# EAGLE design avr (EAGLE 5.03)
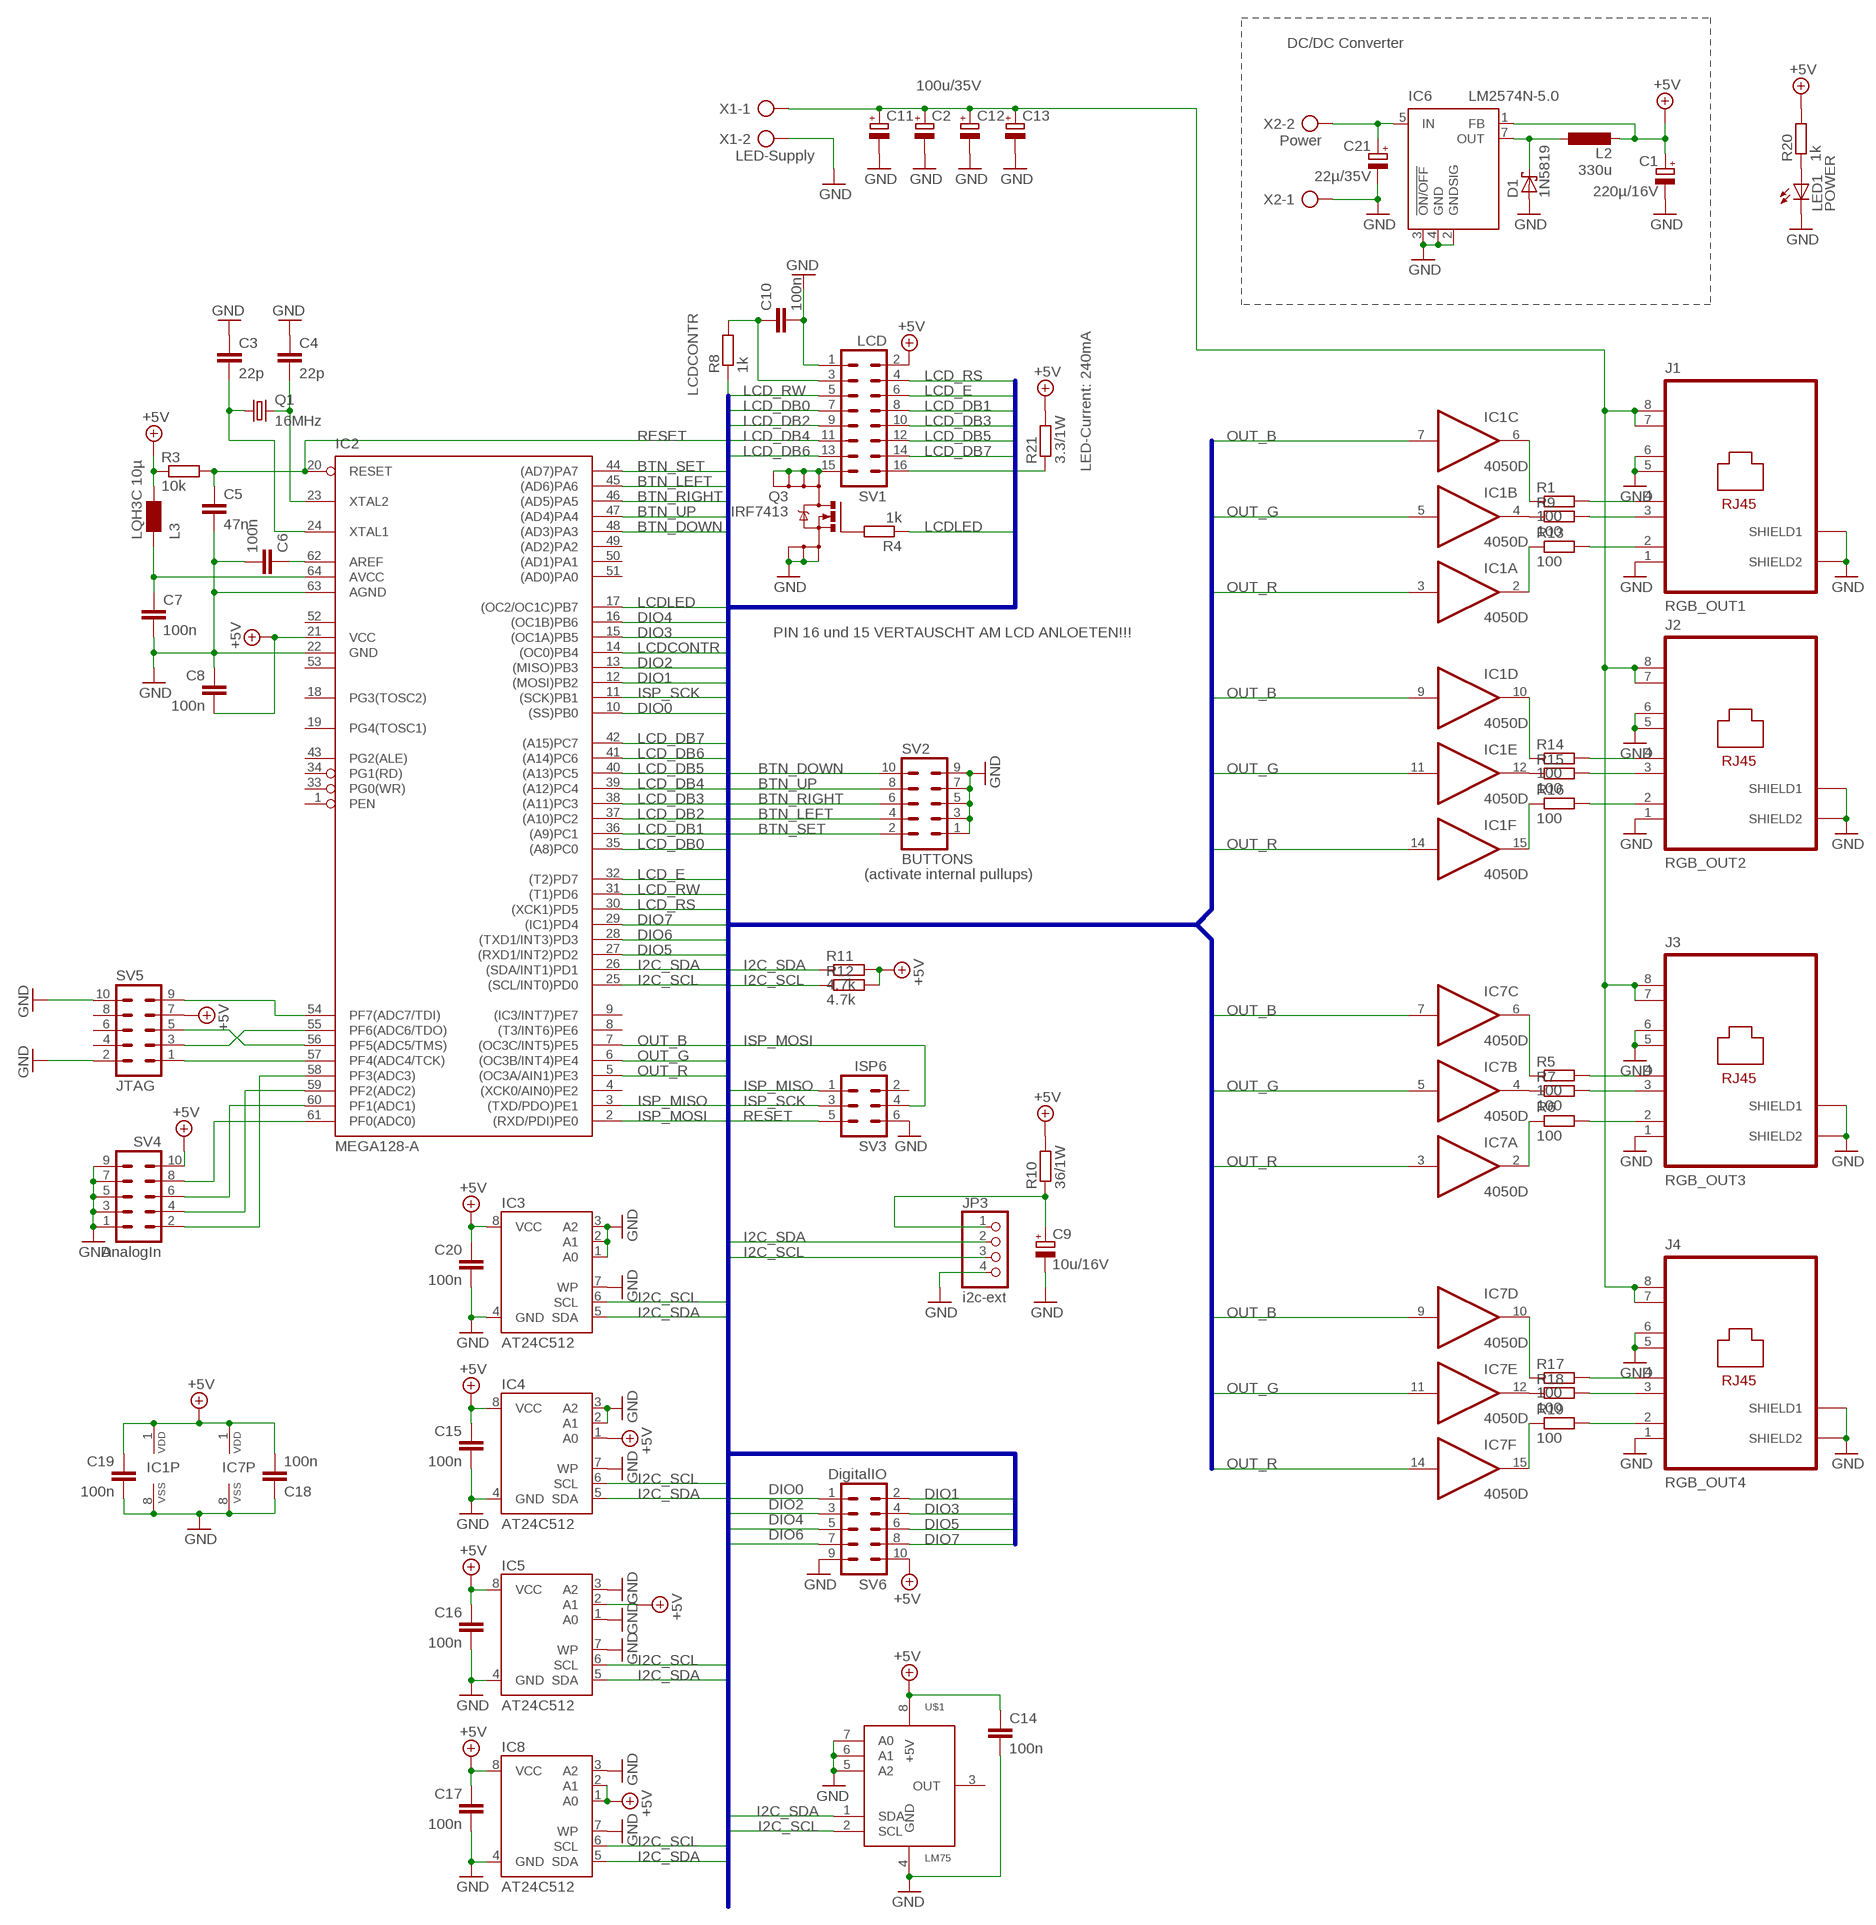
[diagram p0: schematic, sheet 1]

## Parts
C1  220µ/16V  CPOL-EUE2.5-7  [E2,5-7]
C2  100u/35V  CPOL-EUE2.5-7  [E2,5-7]
C3  22p  C-EUC1206  [C1206]
C4  22p  C-EUC1206  [C1206]
C5  47n  C-EUC1206  [C1206]
C6  100n  C-EUC1206  [C1206]
C7  100n  C-EUC1206  [C1206]
C8  100n  C-EUC1206  [C1206]
C9  10u/16V  CPOL-EUE2.5-5  [E2,5-5]
C10  100n  C-EUC1206  [C1206]
C11  100u/35V  CPOL-EUE2.5-7  [E2,5-7]
C12  100u/35V  CPOL-EUE2.5-7  [E2,5-7]
C13  100u/35V  CPOL-EUE2.5-7  [E2,5-7]
C14  100n  C-EUC1206  [C1206]
C15  100n  C-EUC1206  [C1206]
C16  100n  C-EUC1206  [C1206]
C17  100n  C-EUC1206  [C1206]
C18  100n  C-EUC1206  [C1206]
C19  100n  C-EUC1206  [C1206]
C20  100n  C-EUC1206  [C1206]
C21  22µ/35V  CPOL-EUE2.5-5  [E2,5-5]
D1  1N5819  SCHOTTKY-DIODEF126Z12  [F126Z12]
IC1  4050D  [SO16]
IC2  MEGA128-A  [TQFP64]
IC3  AT24C512  AT24CP  [DIL08]
IC4  AT24C512  AT24CP  [DIL08]
IC5  AT24C512  AT24CP  [DIL08]
IC6  LM2574N-5.0  [DIL08]
IC7  4050D  [SO16]
IC8  AT24C512  AT24CP  [DIL08]
J1  RGB_OUT1  MBEP8-8G  [MBEP8-8G]
J2  RGB_OUT2  MBEP8-8G  [MBEP8-8G]
J3  RGB_OUT3  MBEP8-8G  [MBEP8-8G]
J4  RGB_OUT4  MBEP8-8G  [MBEP8-8G]
JP3  i2c-ext  PINHD-1X4  [1X04]
L2  330u  L-EUPIS2816  [PIS2816]
L3  LQH3C 10µ  WE-CBF_1210  [1210]
LED1  POWER  LEDCHIPLED_1206  [CHIPLED_1206]
Q1  16MHz  CRYSTALHC49UP  [HC49UP]
Q3  IRF7413  [SO08]
R1  100  R-EU_R1206  [R1206]
R3  10k  R-EU_R1206  [R1206]
R4  1k  R-EU_R1206  [R1206]
R5  100  R-EU_R1206  [R1206]
R6  100  R-EU_R1206  [R1206]
R7  100  R-EU_R1206  [R1206]
R8  1k  R-EU_R1206  [R1206]
R9  100  R-EU_R1206  [R1206]
R10  36/1W  R-EU_0309/12  [0309/12]
R11  4.7k  R-EU_R1206  [R1206]
R12  4.7k  R-EU_R1206  [R1206]
R13  100  R-EU_R1206  [R1206]
R14  100  R-EU_R1206  [R1206]
R15  100  R-EU_R1206  [R1206]
R16  100  R-EU_R1206  [R1206]
R17  100  R-EU_R1206  [R1206]
R18  100  R-EU_R1206  [R1206]
R19  100  R-EU_R1206  [R1206]
R20  1k  R-EU_R1206  [R1206]
R21  3.3/1W  R-EU_0309/12  [0309/12]
SV1  LCD  ML16  [ML16]
SV2  BUTTONS  ML10  [ML10]
SV3  ISP6  ML6  [ML6]
SV4  AnalogIn  ML10  [ML10]
SV5  JTAG  ML10  [ML10]
SV6  DigitalIO  ML10  [ML10]
U$1  LM75  [SO8]
X1  LED-Supply  AK500/2  [AK500/2]
X2  Power  AK500/2  [AK500/2]

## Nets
+5V: C1.+ C8.2 C14.1 C15.1 C16.1 C17.1 C18.2 C19.1 C20.1 IC1.1(P:VDD) IC2.21(VCC) IC3.8(VCC) IC4.1(A0) IC4.8(VCC) IC5.2(A1) IC5.8(VCC) IC6.1(FB) IC7.1(P:VDD) IC8.1(A0) IC8.2(A1) IC8.8(VCC) L2.2 L3.2 R3.1 R10.2 R11.2 R12.2 R20.2 R21.2 SV1.2 SV4.10 SV5.7 SV6.10 U$1.8(+5V)
BTN_DOWN: IC2.48((AD3)PA3) SV2.10
BTN_LEFT: IC2.45((AD6)PA6) SV2.4
BTN_RIGHT: IC2.46((AD5)PA5) SV2.6
BTN_SET: IC2.44((AD7)PA7) SV2.2
BTN_UP: IC2.47((AD4)PA4) SV2.8
DIO0: IC2.10((SS)PB0) SV6.1
DIO1: IC2.12((MOSI)PB2) SV6.2
DIO2: IC2.13((MISO)PB3) SV6.3
DIO3: IC2.15((OC1A)PB5) SV6.4
DIO4: IC2.16((OC1B)PB6) SV6.5
DIO5: IC2.27((RXD1/INT2)PD2) SV6.6
DIO6: IC2.28((TXD1/INT3)PD3) SV6.7
DIO7: IC2.29((IC1)PD4) SV6.8
GND: C1.- C2.- C3.1 C4.1 C5.2 C6.2 C7.2 C8.1 C9.- C10.2 C11.- C12.- C13.- C14.2 C15.2 C16.2 C17.2 C18.1 C19.2 C20.2 C21.- D1.A IC1.8(P:VSS) IC2.22(GND) IC2.63(AGND) IC3.1(A0) IC3.2(A1) IC3.3(A2) IC3.4(GND) IC3.7(WP) IC4.2(A1) IC4.3(A2) IC4.4(GND) IC4.7(WP) IC5.1(A0) IC5.3(A2) IC5.4(GND) IC5.7(WP) IC6.2(GNDSIG) IC6.3(!ON/OFF) IC6.4(GND) IC7.8(P:VSS) IC8.3(A2) IC8.4(GND) IC8.7(WP) J1.1 J1.5 J1.6 J1.S1(SHIELD1) J1.S2(SHIELD2) J2.1 J2.5 J2.6 J2.S1(SHIELD1) J2.S2(SHIELD2) J3.1 J3.5 J3.6 J3.S1(SHIELD1) J3.S2(SHIELD2) J4.1 J4.5 J4.6 J4.S1(SHIELD1) J4.S2(SHIELD2) JP3.4 LED1.C Q3.1(S) Q3.2(S) Q3.3(S) SV1.1 SV2.1 SV2.3 SV2.5 SV2.7 SV2.9 SV3.6 SV4.1 SV4.3 SV4.5 SV4.7 SV4.9 SV5.2 SV5.10 SV6.9 U$1.4(GND) U$1.5(A2) U$1.6(A1) U$1.7(A0) X1.2 X2.1
I2C_SCL: IC2.25((SCL/INT0)PD0) IC3.6(SCL) IC4.6(SCL) IC5.6(SCL) IC8.6(SCL) JP3.3 R12.1 U$1.2(SCL)
I2C_SDA: IC2.26((SDA/INT1)PD1) IC3.5(SDA) IC4.5(SDA) IC5.5(SDA) IC8.5(SDA) JP3.2 R11.1 U$1.1(SDA)
ISP_MISO: IC2.3((TXD/PDO)PE1) SV3.1
ISP_MOSI: IC2.2((RXD/PDI)PE0) SV3.4
ISP_SCK: IC2.11((SCK)PB1) SV3.3
LCD_DB0: IC2.35((A8)PC0) SV1.7
LCD_DB1: IC2.36((A9)PC1) SV1.8
LCD_DB2: IC2.37((A10)PC2) SV1.9
LCD_DB3: IC2.38((A11)PC3) SV1.10
LCD_DB4: IC2.39((A12)PC4) SV1.11
LCD_DB5: IC2.40((A13)PC5) SV1.12
LCD_DB6: IC2.41((A14)PC6) SV1.13
LCD_DB7: IC2.42((A15)PC7) SV1.14
LCD_E: IC2.32((T2)PD7) SV1.6
LCD_RS: IC2.30((XCK1)PD5) SV1.4
LCD_RW: IC2.31((T1)PD6) SV1.5
LCDCONTR: IC2.14((OC0)PB4) R8.1
LCDLED: IC2.17((OC2/OC1C)PB7) R4.1
LED+: C2.+ C11.+ C12.+ C13.+ J1.7 J1.8 J2.7 J2.8 J3.7 J3.8 J4.7 J4.8 X1.1
N$1: C3.2 IC2.24(XTAL1) Q1.1
N$2: C4.2 IC2.23(XTAL2) Q1.2
N$3: IC1.2(A:O) R13.1
N$4: C10.1 R8.2 SV1.3
N$5: J1.4 R1.2
N$6: J1.3 R9.2
N$7: J1.2 R13.2
N$8: J2.4 R14.2
N$9: J2.3 R15.2
N$10: J2.2 R16.2
N$11: IC1.4(B:O) R9.1
N$12: IC1.6(C:O) R1.1
N$13: IC1.15(F:O) R16.1
N$15: IC1.12(E:O) R15.1
N$16: IC1.10(D:O) R14.1
N$17: C7.1 IC2.64(AVCC) L3.1
N$18: IC2.59(PF2(ADC2)) SV4.4
N$19: J3.4 R5.2
N$20: J3.3 R7.2
N$21: C6.1 IC2.62(AREF)
N$22: IC2.61(PF0(ADC0)) SV4.8
N$23: J3.2 R6.2
N$24: J4.4 R17.2
N$25: C9.+ JP3.1 R10.1
N$26: J4.3 R18.2
N$27: J4.2 R19.2
N$28: IC7.2(A:O) R6.1
N$29: IC2.60(PF1(ADC1)) SV4.6
N$30: Q3.4(G) R4.2
N$31: IC7.4(B:O) R7.1
N$32: IC7.6(C:O) R5.1
N$33: C21.+ IC6.5(IN) X2.2
N$34: Q3.5(D) Q3.6(D) Q3.7(D) Q3.8(D) SV1.15
N$35: IC7.12(E:O) R18.1
N$36: IC7.10(D:O) R17.1
N$37: D1.C IC6.7(OUT) L2.1
N$38: IC7.15(F:O) R19.1
N$39: LED1.A R20.1
N$40: R21.1 SV1.16
N$41: IC2.57(PF4(ADC4/TCK)) SV5.1
N$42: IC2.55(PF6(ADC6/TDO)) SV5.3
N$43: IC2.56(PF5(ADC5/TMS)) SV5.5
N$44: IC2.54(PF7(ADC7/TDI)) SV5.9
N$52: IC2.58(PF3(ADC3)) SV4.2
OUT_B: IC1.7(C:I) IC1.9(D:I) IC2.7((OC3C/INT5)PE5) IC7.7(C:I) IC7.9(D:I)
OUT_G: IC1.5(B:I) IC1.11(E:I) IC2.6((OC3B/INT4)PE4) IC7.5(B:I) IC7.11(E:I)
OUT_R: IC1.3(A:I) IC1.14(F:I) IC2.5((OC3A/AIN1)PE3) IC7.3(A:I) IC7.14(F:I)
RESET: C5.1 IC2.20(RESET) R3.2 SV3.5
Unconnected: IC2.1(PEN) IC2.4((XCK0/AIN0)PE2) IC2.8((T3/INT6)PE6) IC2.9((IC3/INT7)PE7) IC2.18(PG3(TOSC2)) IC2.19(PG4(TOSC1)) IC2.33(PG0(WR)) IC2.34(PG1(RD)) IC2.43(PG2(ALE)) IC2.49((AD2)PA2) IC2.50((AD1)PA1) IC2.51((AD0)PA0) SV3.2 SV5.4 SV5.6 SV5.8 U$1.3(OUT)

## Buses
B$5

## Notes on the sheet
- DC/DC Converter
- LED-Current: 240mA
- PIN 16 und 15 VERTAUSCHT AM LCD ANLOETEN!!!
- (activate internal pullups)

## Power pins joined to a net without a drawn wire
GND1: IC2.53(GND1)
VCC1: IC2.52(VCC1)

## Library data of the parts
C1 C2 C9 C11-C13 C21 = rcl:CPOL-EU: POLARIZED CAPACITOR, European symbol
C3-C8 C10 C14-C20 = rcl:C-EU: CAPACITOR, European symbol
D1 = diode:SCHOTTKY-DIODE: Schottky Diode
IC1 IC7 = 40xx:4050: Hex non-inverting BUFFER
IC2 = atmel:MEGA128: MICROCONTROLLER 128 Kbytes FLASH 4 Kbytes SRAM 4 Kbytes EEPROM DUAL USART 8-channel 10 bit ADC Source: avr.lbr
IC3-IC5 IC8 = atmel:AT24C*: 2-wire serial EEPROM
IC6 = linear:LM2574?-*: SIMPLE SWITCHER 0.5A Step-Down Voltage Regulator Source: http://cache.national.com/ds/LM/LM2574.pdf
J1-J4 = own:MBEP8-8G: Distributor: Reichelt.de
JP3 = pinhead:PINHD-1X4: PIN HEADER
L2 = rcl:L-EU: INDUCTOR, European symbol
L3 = wuerth-elektronik:WE-CBF: SMD EMI Suppression Ferrite Beads
LED1 = led:LED: LED
Q1 = crystal:CRYSTAL: CRYSTAL
Q3 = own:IRF7413: HEXFET Power MOSFET
R1 R3-R21 = rcl:R-EU_: RESISTOR, European symbol
SV1 = con-harting-ml:ML16: HARTING
SV2 SV4-SV6 = con-harting-ml:ML10: HARTING
SV3 = con-harting-ml:ML6: HARTING
U$1 = lm75:LM75
X1 X2 = con-ptr500:AK500/2: CONNECTOR

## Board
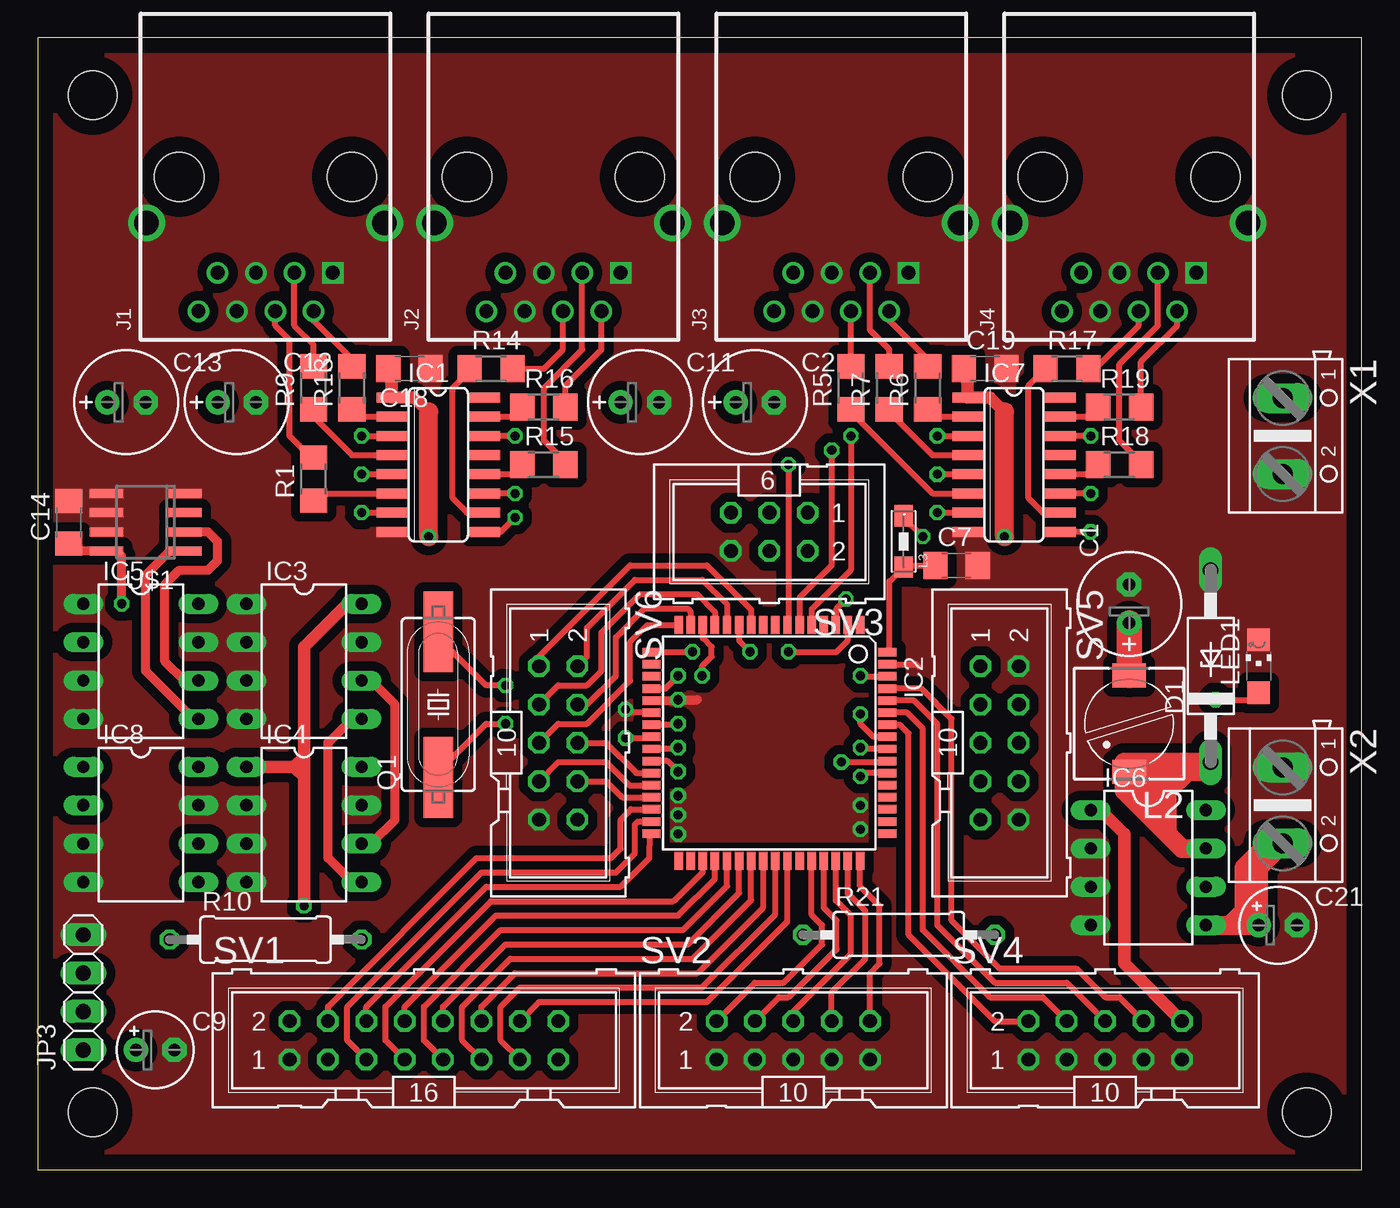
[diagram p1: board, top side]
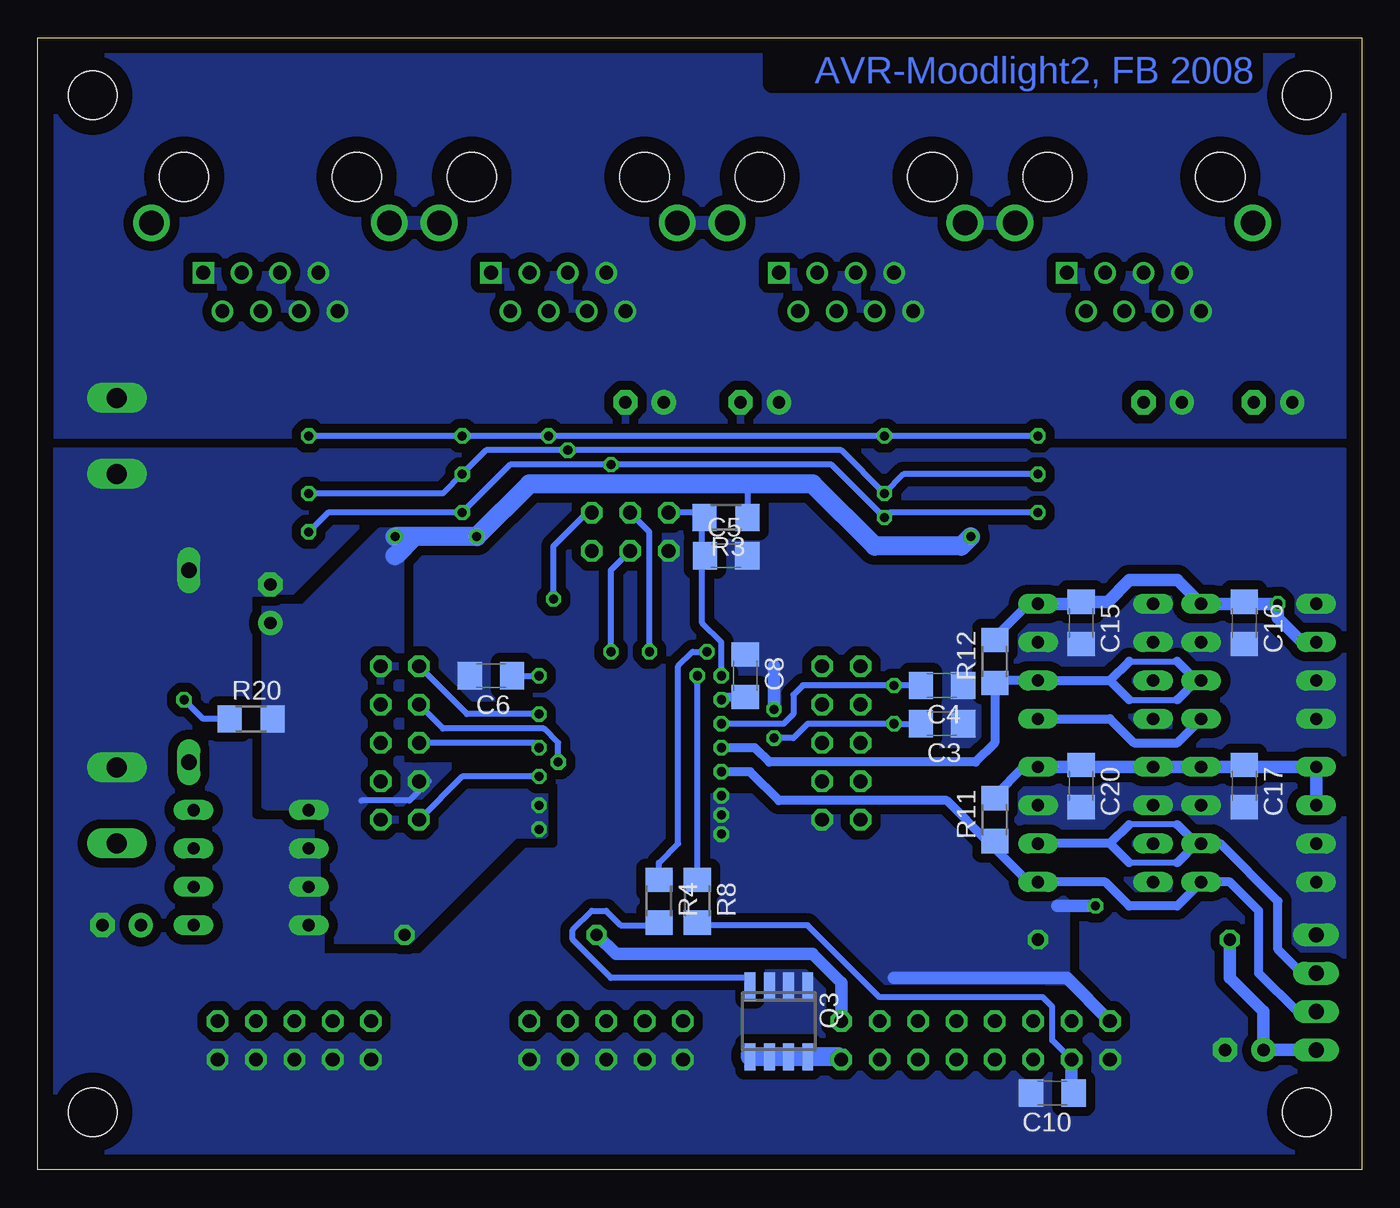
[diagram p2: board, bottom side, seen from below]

Size 87.62 x 74.92 mm. Coordinates in mm from the lower left corner, seen from the top.
Outline: 0,0 87.62,0 87.62,74.92 0,74.92 0,0
Copper layers (1*16): Top 0.035mm / dielectric 1.5mm / Bottom 0.035mm
Design rules "default": minimum track width 10mil, minimum drill 24mil, track to track 8mil, track to pad 8mil, pad to pad 8mil, via to via 8mil, smd to smd 8mil, copper to edge 40mil, drill to drill 8mil, minimum pad ring 10mil, minimum via ring 8mil, stop-mask expansion 4mil, vias tented up to drill 0mil, thermal gap 10mil
Holes 3.2 mm at 3.64,3.8 3.64,71.11 83.97,3.8 83.97,71.11

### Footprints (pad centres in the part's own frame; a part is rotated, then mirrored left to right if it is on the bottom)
E2,5-7 = drill 0.813 pad 1.6 round: + -1.27,0 | drill 0.813 pad 1.6 octagon: - 1.27,0
C1206 = smd 1.6 x 1.8: 1 -1.4,0; 2 1.4,0
E2,5-5 = drill 0.813 pad 1.6 round: + -1.27,0 | drill 0.813 pad 1.6 octagon: - 1.27,0
F126Z12 = drill 1.016 long: A 6.35,0; C -6.35,0
SO16 = smd 0.66 x 2.032: 1 -4.445,-3.073; 2 -3.175,-3.073; 3 -1.905,-3.073; 4 -0.635,-3.073; 5 0.635,-3.073; 6 1.905,-3.073; 7 3.175,-3.073; 8 4.445,-3.073; 9 4.445,3.073; 10 3.175,3.073; 11 1.905,3.073; 12 0.635,3.073; 13 -0.635,3.073; 14 -1.905,3.073; 15 -3.175,3.073; 16 -4.445,3.073
TQFP64 = smd 1.194 x 0.559: 1 -7.8,6; 2 -7.8,5.2; 3 -7.8,4.4; 4 -7.8,3.6; 5 -7.8,2.8; 6 -7.8,2; 7 -7.8,1.2; 8 -7.8,0.4; 9 -7.8,-0.4; 10 -7.8,-1.2; 11 -7.8,-2; 12 -7.8,-2.8; 13 -7.8,-3.6; 14 -7.8,-4.4; 15 -7.8,-5.2; 16 -7.8,-6; 33 7.8,-6; 34 7.8,-5.2; 35 7.8,-4.4; 36 7.8,-3.6; 37 7.8,-2.8; 38 7.8,-2; 39 7.8,-1.2; 40 7.8,-0.4; 41 7.8,0.4; 42 7.8,1.2; 43 7.8,2; 44 7.8,2.8; 45 7.8,3.6; 46 7.8,4.4; 47 7.8,5.2; 48 7.8,6 | smd 0.559 x 1.194: 17 -6,-7.8; 18 -5.2,-7.8; 19 -4.4,-7.8; 20 -3.6,-7.8; 21 -2.8,-7.8; 22 -2,-7.8; 23 -1.2,-7.8; 24 -0.4,-7.8; 25 0.4,-7.8; 26 1.2,-7.8; 27 2,-7.8; 28 2.8,-7.8; 29 3.6,-7.8; 30 4.4,-7.8; 31 5.2,-7.8; 32 6,-7.8; 49 6,7.8; 50 5.2,7.8; 51 4.4,7.8; 52 3.6,7.8; 53 2.8,7.8; 54 2,7.8; 55 1.2,7.8; 56 0.4,7.8; 57 -0.4,7.8; 58 -1.2,7.8; 59 -2,7.8; 60 -2.8,7.8; 61 -3.6,7.8; 62 -4.4,7.8; 63 -5.2,7.8; 64 -6,7.8
DIL08 = drill 0.813 long: 1 -3.81,-3.81; 2 -1.27,-3.81; 3 1.27,-3.81; 4 3.81,-3.81; 5 3.81,3.81; 6 1.27,3.81; 7 -1.27,3.81; 8 -3.81,3.81
MBEP8-8G = drill 0.914 square: 1 4.445,-6.35 | drill 0.914 round: 2 3.175,-8.89; 3 1.905,-6.35; 4 0.635,-8.89; 5 -0.635,-6.35; 6 -1.905,-8.89; 7 -3.175,-6.35; 8 -4.445,-8.89 | drill 1.626 round: S1 -7.874,-3.048; S2 7.874,-3.048 | hole 3.251: -5.715,0; 5.715,0
1X04 = drill 1.016 long: 1 -3.81,0; 2 -1.27,0; 3 1.27,0; 4 3.81,0
PIS2816 = smd 2.2 x 1.6: 1 0,3.2; 2 0,-3.2
1210 = smd 1.4 x 1.2: 1 -1.7,0; 2 1.7,0
CHIPLED_1206 = smd 1.5 x 1.5: A 0,-1.75; C 0,1.75
HC49UP = smd 5.334 x 1.93: 1 -4.826,0; 2 4.826,0
SO08 = smd 0.72 x 1.78: 1 -1.905,-2.35; 2 -0.635,-2.35; 3 0.635,-2.35; 4 1.905,-2.35; 5 1.905,2.35; 6 0.635,2.35; 7 -0.635,2.35; 8 -1.905,2.35
R1206 = smd 1.6 x 1.803: 1 -1.422,0; 2 1.422,0
0309/12 = drill 0.813 octagon: 1 -6.35,0; 2 6.35,0
ML16 = drill 0.914 octagon: 1 -8.89,-1.27; 2 -8.89,1.27; 3 -6.35,-1.27; 4 -6.35,1.27; 5 -3.81,-1.27; 6 -3.81,1.27; 7 -1.27,-1.27; 8 -1.27,1.27; 9 1.27,-1.27; 10 1.27,1.27; 11 3.81,-1.27; 12 3.81,1.27; 13 6.35,-1.27; 14 6.35,1.27; 15 8.89,-1.27; 16 8.89,1.27
ML10 = drill 0.914 octagon: 1 -5.08,-1.27; 2 -5.08,1.27; 3 -2.54,-1.27; 4 -2.54,1.27; 5 0,-1.27; 6 0,1.27; 7 2.54,-1.27; 8 2.54,1.27; 9 5.08,-1.27; 10 5.08,1.27
ML6 = drill 0.914 octagon: 1 -2.54,-1.27; 2 -2.54,1.27; 3 0,-1.27; 4 0,1.27; 5 2.54,-1.27; 6 2.54,1.27
SO8 = smd 0.6 x 2.2: 1 -1.905,-2.6; 2 -0.635,-2.6; 3 0.635,-2.6; 4 1.905,-2.6; 5 1.905,2.6; 6 0.635,2.6; 7 -0.635,2.6; 8 -1.905,2.6
AK500/2 = drill 1.321 long: 1 -2.515,0; 2 2.515,0

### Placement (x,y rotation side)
C1  72.22,37.46 90 top
C2  47.46,50.8 0 top
C3  27.77,29.52 180 bottom
C4  27.77,32.06 180 bottom
C5  42.06,40.64 0 bottom
C6  57.62,32.7 180 bottom
C7  60.8,40 0 top
C8  40.79,32.7 270 bottom
C9  7.77,7.93 0 top
C10  20.47,5.08 180 bottom
C11  39.84,50.8 0 top
C12  13.17,50.8 0 top
C13  5.87,50.8 0 top
C14  2.06,42.86 90 top
C15  18.57,36.19 270 bottom
C16  7.77,36.19 270 bottom
C17  7.77,25.39 270 bottom
C18  24.6,53.02 180 top
C19  62.7,53.02 0 top
C20  18.57,25.39 270 bottom
C21  82.07,16.19 0 top
D1  77.62,33.33 90 top
IC1  26.5,46.67 270 top
IC2  48.41,28.25 270 top
IC3  17.61,33.65 270 top
IC4  17.61,22.86 270 top
IC5  6.82,33.65 270 top
IC6  73.5,20 270 top
IC7  64.61,46.67 270 top
IC8  6.82,22.86 270 top
J1  15.08,65.72 0 top
J2  34.12,65.72 0 top
J3  53.17,65.72 0 top
J4  72.22,65.72 0 top
JP3  3.01,11.74 90 top
L2  72.22,29.52 180 top
L3  57.3,41.59 90 top
LED1  80.8,33.33 0 top
Q1  26.5,30.79 90 top
Q3  38.57,9.84 180 bottom
R1  18.25,45.72 90 top
R3  42.06,43.18 180 bottom
R4  46.51,17.77 270 bottom
R5  53.81,51.75 90 top
R6  58.89,51.75 90 top
R7  56.35,51.75 90 top
R8  43.97,17.77 270 bottom
R9  18.25,51.75 90 top
R10  15.08,15.24 0 top
R11  24.28,23.17 90 bottom
R12  24.28,33.65 90 bottom
R13  20.79,51.75 90 top
R14  30,53.02 0 top
R15  33.49,46.67 0 top
R16  33.49,50.48 0 top
R17  68.1,53.02 0 top
R18  71.59,46.67 0 top
R19  71.59,50.48 0 top
R20  73.5,29.84 0 bottom
R21  56.98,15.55 0 top
SV1  25.55,8.57 0 top
SV2  50,8.57 0 top
SV3  48.41,42.22 180 top
SV4  70.64,8.57 0 top
SV5  63.65,28.25 270 top
SV6  34.44,28.25 270 top
U$1  7.14,42.86 90 top
X1  82.39,48.57 270 top
X2  82.39,24.12 270 top

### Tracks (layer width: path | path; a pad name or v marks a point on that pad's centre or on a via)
+5V  (via drill 0.6)
  Top 0.406: L3.2 57.3,43.18 v58.57,41.91
  Top 0.61: IC2.21 42.64,31.05 v42.38,31.11 43.65,31.11 | v5.55,37.46 5.55,40.64 5.23,40.95 U$1.8 2.38,40.95 2.06,41.27 C14.1
  Top 0.813: 25.87,50.16 24.92,51.11 IC1.1 23.43,52.92 23.33,53.02 C18.2 | 63.97,50.16 63.02,51.11 IC7.1 61.53,52.92 61.43,53.02 C19.1 | IC6.1 70.32,23.81 71.91,22.22 71.91,13.65 SV4.10 | IC3.8 20.47,37.46 17.61,34.6 17.61,27.3 | 17.61,26.66 17.61,27.3 | IC4.1 16.98,26.66 | 16.98,26.66 17.61,26.66 | 17.61,26.66 17.61,26.03 | 16.98,26.66 17.61,27.3 | 17.61,27.3 17.61,26.03 | 16.98,26.66 17.61,26.03 | 17.61,26.03 v17.61,17.46
  Top 1.27: v63.97,41.91 63.97,50.16 | v25.87,41.91 25.87,50.16
  Top 1.676: L2.2 C1.+
  Bottom 0.406: SV5.7 61.75,25.71 63.02,24.44 66.19,24.44 | R3.1 40.64,45.25 40.79,45.4
  Bottom 0.61: C8.2 42.19,31.3 v42.38,31.11 | 7.77,26.66 C17.1 | 7.77,37.46 C16.1 | R12.2 24.28,35.24 22.06,37.46 IC3.8 | 24.28,24.44 R11.2 24.28,24.76 22.38,26.66 IC4.8
  Bottom 0.813: SV1.2 19.52,12.7 30.95,12.7 | 18.57,26.66 IC4.1 IC8.8 7.77,26.66 IC8.1 IC8.2 | 18.57,26.66 C20.1 | 18.57,26.66 IC4.8 | IC3.8 18.88,37.46 18.75,37.59 C15.1 16.79,37.59 15.39,39.05 12.22,39.05 IC5.8 7.77,37.46 v5.55,37.46 5.55,36.51 3.96,34.92 IC5.2 | v17.61,17.46 20.15,17.46
  Bottom 1.27: v25.87,41.91 26.5,41.27 32.22,41.27 36.35,45.4 40.79,45.4 55.08,45.4 v58.57,41.91 62.7,41.91 | 62.7,41.91 v63.97,41.91 | 62.7,41.91 63.97,40.64
  other vias: 54.45,24.12 54.45,22.54 42.38,22.22 42.38,23.49 42.38,24.76
  pour Top (isolate 0.61, rank 3, no thermals): 41.43,35.24 41.43,20.95 55.4,21.27 55.4,35.24
  pour Bottom (isolate 0.61, rank 3, no thermals): 72.54,37.14 72.54,24.12 68.41,24.12 68.41,15.24 63.02,15.24 56.03,22.22 54.13,22.22 54.13,26.66 63.65,26.66 63.65,42.22 64.92,42.22 70,37.14
  pour Bottom (isolate 0.61, rank 3, no thermals): 19.52,17.77 19.52,12.38 33.49,12.38 35.08,13.97 43.02,13.97 43.02,24.76 26.5,24.76
BTN_DOWN
  Top 0.406: IC2.48 54.41,18.76 55.71,17.46 55.71,13.65 55.08,13.01 SV2.10
BTN_LEFT
  Top 0.406: SV2.4 49.05,11.43 49.68,11.43 52.86,14.6 52.86,16.5 52.22,17.14 | 52.22,17.14 52.12,17.25 | IC2.45 52.01,17.35 52.22,17.14
BTN_RIGHT
  Top 0.406: IC2.46 52.81,17.82 53.81,16.82 53.81,14.28 49.95,10.43 SV2.6
BTN_SET
  Top 0.406: SV2.2 47.46,12.38 49.37,12.38 51.91,14.92 51.91,16.19 51.21,16.88 IC2.44
BTN_UP
  Top 0.406: IC2.47 53.61,18.29 54.76,17.14 54.76,13.97 52.54,11.74 SV2.8
DIO0
  Top 0.406: IC2.10 47.21,37.07 44.28,40 39.2,40 33.17,33.97 SV6.1
DIO1
  Top 0.406: IC2.12 45.61,37.4 43.97,39.05 39.52,39.05 36.35,35.87 36.35,33.97 SV6.2
DIO2
  Top 0.406: IC2.13 44.81,36.93 43.65,38.1 39.84,38.1 37.3,35.55 37.3,33.02 36.35,32.06 34.44,32.06 SV6.3
DIO3
  Top 0.406: IC2.15 43.21,36.95 43.02,37.14 40.16,37.14 38.25,35.24 38.25,32.7 36.35,30.79 SV6.4
DIO4
  Top 0.406: IC2.16 40.34,36.05 39.2,34.92 39.2,32.38 36.35,29.52 34.44,29.52 SV6.5
DIO5
  Top 0.406: IC2.27 39.62,26.25 37.62,28.25 SV6.6
DIO6
  Top 0.406: IC2.28 39.15,25.45 37.62,26.98 34.44,26.98 SV6.7
DIO7
  Top 0.406: IC2.29 38.68,24.65 38.57,24.76 37.62,25.71 SV6.8
GND  (via drill 0.6)
  Top 0.406: IC2.63 58.13,33.45 58.25,33.33 | IC2.22 39.3,30.25 v38.89,30.47
  Bottom 0.813: v38.89,30.47 38.89,33.33
  pour Top (isolate 0.61, rank 6, no thermals): -1.44,78.42 -1.44,-1.91 90,-1.91 90,78.42
  pour Bottom (isolate 0.61, rank 6, no thermals): -2.71,78.73 -2.71,-3.18 93.81,-2.86 93.81,78.73
I2C_SCL  (via drill 0.6)
  Top 0.406: IC2.25 42.14,27.85 v42.38,27.93
  Top 0.61: U$1.2 11.27,42.22 11.9,41.59 11.9,40.32 11.27,39.68 9.36,39.68 8.41,38.73 8.41,33.65 9.68,32.38 IC5.6 | IC3.6 22.06,32.38 23.65,30.79 23.65,23.17 22.06,21.58 IC4.6
  Bottom 0.406: 15.39,31.11 12.22,31.11 | 12.22,20.31 15.39,20.31 | 15.39,33.65 12.22,33.65 | 12.22,22.86 15.39,22.86
  Bottom 0.61: v42.38,27.93 40.16,27.93 39.2,26.98 25.55,26.98 24.28,28.25 R12.1 24.28,32.38 IC3.6 16.66,32.38 | 12.22,31.11 10.95,32.38 | 16.66,32.38 15.39,31.11 | 10.95,21.58 12.22,20.31 | 15.39,20.31 16.66,21.58 | 16.66,21.58 IC4.6 | 10.95,32.38 IC5.6 | 12.22,33.65 10.95,32.38 | 16.66,32.38 15.39,33.65 | 10.95,21.58 IC8.6 9.36,21.58 5.55,17.77 5.55,14.6 3.96,13.01 JP3.3 | 10.95,21.58 12.22,22.86 | 15.39,22.86 16.66,21.58
I2C_SDA  (via drill 0.6)
  Top 0.406: v42.38,26.35 41.67,27.05 IC2.26
  Top 0.61: IC4.5 20.79,19.04 19.2,20.63 19.2,28.25 20.79,29.84 IC3.5 | U$1.1 8.73,40.95 7.14,39.37 7.14,33.02 10.31,29.84 IC5.5
  Bottom 0.61: v42.38,26.35 40.48,26.35 38.57,24.44 27.46,24.44 24.76,21.74 | 24.76,21.74 24.6,21.58 | IC5.5 12.22,28.25 15.08,28.25 16.66,29.84 IC3.5 | JP3.2 4.28,10.47 6.82,13.01 6.82,17.14 8.73,19.04 IC8.5 12.22,17.46 15.39,17.46 16.98,19.04 IC4.5 22.06,19.04 24.28,21.27 R11.1 24.45,21.75 24.6,21.9 24.76,21.74 | 24.76,21.74
ISP_MISO  (via drill 0.6)
  Top 0.406: v53.49,37.78 52.86,37.14 52.86,36.05 IC2.3
  Bottom 0.406: v53.49,37.78 53.49,41.27 51.27,43.49 SV3.1
ISP_MOSI  (via drill 0.6)
  Top 0.406: IC2.2 53.61,35.04 52.86,34.29 v49.68,34.29
  Bottom 0.406: v49.68,34.29 49.68,39.68 SV3.4
ISP_SCK  (via drill 0.6)
  Top 0.406: IC2.11 46.41,35.02 v47.14,34.29
  Bottom 0.406: SV3.3 47.14,42.22 v47.14,34.29
LCD_DB0
  Top 0.406: IC2.35 44.01,19.72 42.06,17.77 30,17.77 23.01,10.79 23.01,8.57 SV1.7
LCD_DB1
  Top 0.406: IC2.36 44.81,19.25 42.38,16.82 30.31,16.82 24.28,10.79 SV1.8
LCD_DB2
  Top 0.406: IC2.37 45.61,18.79 42.7,15.87 30.63,15.87 25.55,10.79 25.55,8.57 SV1.9
LCD_DB3
  Top 0.406: IC2.38 46.41,18.31 43.02,14.92 30.95,14.92 26.82,10.79 SV1.10
LCD_DB4
  Top 0.406: IC2.39 47.21,17.84 43.33,13.97 31.27,13.97 28.09,10.79 28.09,8.57 SV1.11
LCD_DB5
  Top 0.406: IC2.40 48.01,17.38 43.65,13.01 31.58,13.01 29.36,10.79 SV1.12
LCD_DB6
  Top 0.406: IC2.41 48.81,16.9 43.97,12.06 31.9,12.06 30.63,10.79 30.63,8.57 SV1.13
LCD_DB7
  Top 0.406: IC2.42 49.61,16.43 44.28,11.11 33.17,11.11 SV1.14
LCD_E
  Top 0.406: IC2.32 40.51,22.25 40.48,20.63 38.57,18.73 29.68,18.73 21.74,10.79 SV1.6
LCD_RS
  Top 0.406: IC2.30 39.25,23.85 38.57,23.17 38.57,21.27 37.94,20.63 29.04,20.63 19.2,10.79 SV1.4
LCD_RW
  Top 0.406: IC2.31 39.72,23.05 39.52,22.86 39.52,20.95 38.25,19.68 29.36,19.68 20.47,10.79 20.47,8.57 SV1.5
LCDCONTR  (via drill 0.6)
  Top 0.406: IC2.14 44.01,35.19 44.6,34.6 44.6,33.97 43.97,33.33 44.01,32.74 v43.97,32.7
  Bottom 0.406: R8.1 v43.97,32.7
LCDLED  (via drill 0.6)
  Top 0.406: IC2.17 43.37,34.25 v43.33,34.29
  Bottom 0.406: v43.33,34.29 44.28,34.29 45.24,33.33 45.24,21.58 46.51,20.31 R4.1 46.51,19.04
LED+
  pour Bottom (isolate 0.61, rank 3, no thermals): 0.79,74.29 0.47,48.57 86.83,48.57 86.83,73.97
N$1  (via drill 0.6)
  Top 0.406: 40.56,28.65 IC2.24 40.24,28.65 40.16,28.57 v38.89,28.57 | Q1.1 26.5,26.35 29.68,29.52 v30.95,29.52
  Bottom 0.406: v38.89,28.57 37.62,28.57 36.66,29.52 v30.95,29.52 C3.2 29.04,29.52
N$2  (via drill 0.6)
  Top 0.406: IC2.23 42.31,29.45 v42.38,29.52 | v30.95,32.06 29.68,32.06 26.5,35.24 Q1.2
  Bottom 0.406: v42.38,29.52 38.25,29.52 37.62,30.16 37.62,31.43 36.98,32.06 v30.95,32.06 C4.2
N$3
  Top 0.406: R13.1 20.79,50.48 21.42,49.84 IC1.2
N$4
  Bottom 0.406: SV1.3 20.47,8.57 20.47,10.79 21.11,11.43 31.9,11.43 36.66,16.19 41.11,16.19 | 41.11,16.19 41.43,16.19 | R8.2 43.97,16.19 41.11,16.19
  Bottom 0.813: C10.1 19.2,5.08 SV1.3
N$5
  Top 0.406: J1.4 15.71,55.88 16.66,54.92 16.66,48.57 17.93,47.3 R1.2
N$6
  Top 0.406: J1.3 16.98,55.88 18.25,54.61 18.25,53.65 18.57,53.34 18.4,53.17 R9.2
N$7
  Top 0.406: R13.2 20.79,53.65 18.25,56.19 J1.2
N$8
  Top 0.406: R14.2 31.42,52.85 31.9,53.02 33.49,53.02 34.76,54.29 J2.4
N$9
  Top 0.406: J2.3 36.03,54.29 33.49,51.75 33.49,48.26 34.91,46.83 R15.2
N$10
  Top 0.406: R16.2 34.91,51.9 37.3,54.29 J2.2
N$11
  Top 0.406: R9.1 18.25,49.84 20.79,47.3 IC1.4
N$12
  Top 0.406: R1.1 18.25,44.45 18.57,44.76 IC1.6
N$13
  Top 0.406: IC1.15 31.9,49.84 32.22,50.16 32.07,50.31 R16.1
N$15
  Top 0.406: IC1.12 32.22,46.03 32.22,46.67 R15.1
N$16
  Top 0.406: IC1.10 28.41,43.49 27.46,44.45 27.46,51.75 28.57,52.87 R14.1
N$17
  Top 0.406: C7.1 57.3,40 L3.1 56.35,38.94 56.35,34.29 56.24,34.29 IC2.64
N$18
  Top 0.406: IC2.59 57.52,30.25 58.57,29.2 58.57,15.87 63.02,11.43 66.51,11.43 SV4.4
N$19
  Top 0.406: R5.2 J3.4
N$20
  Top 0.406: 56.35,53.02 R7.2 56.35,54.29 55.08,55.56 J3.3
N$21  (via drill 0.6)
  Top 0.406: IC2.62 54.49,32.65 v54.45,32.7
  Bottom 0.406: C6.1 v54.45,32.7
N$22
  Top 0.406: IC2.61 58.46,31.85 60.48,29.84 60.48,16.5 63.65,13.33 68.73,13.33 70.64,11.43 71.59,11.43 SV4.8
N$23
  Top 0.406: R6.2 58.89,53.65 56.35,56.19 J3.2
N$24
  Top 0.406: R17.2 70,53.02 72.86,55.88 J4.4
N$25
  Bottom 0.813: JP3.1 C9.+ 6.5,10.47 8.73,12.7 R10.1
N$26
  Top 0.406: J4.3 74.13,55.88 71.59,53.34 71.59,48.26 73.18,46.67 R18.2
N$27
  Top 0.406: R19.2 73.01,53.49 75.4,55.88 J4.2
N$28
  Top 0.406: R6.1 58.89,49.84 IC7.2
N$29
  Top 0.406: IC2.60 57.99,31.05 59.52,29.52 59.52,16.19 63.34,12.38 68.1,12.38 SV4.6
N$30
  Bottom 0.406: Q3.4 40.35,11.87 40.48,12.06 40.48,12.7 49.68,12.7 52.22,15.24 52.22,15.87 50.95,17.14 50,17.14 49.05,16.19 46.51,16.19 R4.2
N$31
  Top 0.406: R7.1 56.35,50.16 59.21,47.3 IC7.4
N$32
  Top 0.406: R5.1 53.81,50.16 59.21,44.76 IC7.6
N$33
  Top 1.27: 82.39,21.58 X2.2 | 82.39,21.58 80.8,20 C21.+ IC6.5 78.89,16.19 79.84,17.14 79.84,20 81.43,21.58 82.39,21.58
N$34
  Bottom 1.27: Q3.5 40.48,7.62 40.35,7.49 Q3.6 39.2,7.62 39.08,7.49 Q3.7 37.94,7.62 37.81,7.49 Q3.8 34.63,7.49 SV1.15
N$35
  Top 0.406: R18.1 70.17,46.52 69.69,46.03 IC7.12
N$36
  Top 0.406: R17.1 65.56,51.9 65.56,44.45 66.51,43.49 IC7.10
N$37
  Top 1.27: L2.1 72.22,26.35 74.77,26.35 | 76.35,26.35 76.99,26.35 D1.C 71.91,26.98 71.91,25.39 | IC6.7 75.72,21.27 75.08,21.9 | 75.08,21.9 74.77,22.22 74.77,25.08 | 74.77,25.08 74.77,26.35 | 75.08,21.9 71.91,25.08 71.91,25.39 | 71.91,25.39 71.91,26.35 74.45,23.81 74.45,25.39 73.81,26.03 74.45,26.03 74.77,26.35 | 76.35,26.35 74.77,26.35 | 76.35,26.35 76.03,26.35 74.77,25.08
N$38
  Top 0.406: IC7.15 70.32,49.84 70.32,50.48 R19.1
N$39  (via drill 0.6)
  Top 0.406: LED1.A 80.8,31.43 80.48,31.11 v77.94,31.11
  Bottom 0.406: R20.1 76.67,29.84 v77.94,31.11
N$40
  Bottom 0.813: R21.1 49.37,14.28 36.35,14.28 34.44,12.38 SV1.16
N$41  (via drill 0.6)
  Top 0.406: IC2.57 55.31,28.65 54.45,29.52 v54.45,30.16
  Bottom 0.406: v54.45,30.16 59.21,30.16 SV5.1
N$42  (via drill 0.6)
  Top 0.406: IC2.55 56.1,27.05 56.03,26.98 v53.17,26.98
  Bottom 0.406: v53.17,26.98 53.17,28.25 54.13,29.2 60.8,29.2 SV5.3
N$43  (via drill 0.6)
  Top 0.406: IC2.56 54.53,27.85 v54.45,27.93
  Bottom 0.406: v54.45,27.93 54.76,28.25 SV5.5
N$44  (via drill 0.6)
  Top 0.406: IC2.54 54.67,26.25 v54.45,26.03
  Bottom 0.406: v54.45,26.03 59.52,26.03 SV5.9
N$52
  Top 0.406: IC2.58 57.05,29.45 57.62,28.89 57.62,15.55 63.34,9.84 SV4.2
OUT_B  (via drill 0.6)
  Top 0.406: v31.58,43.18 30.63,42.22 IC1.9 | v21.42,43.49 IC1.7 | v69.69,42.22 IC7.9 | v59.52,43.49 IC7.7 | IC2.7 49.61,36.12 49.68,36.19 v49.68,46.67
  Bottom 0.406: v21.42,43.49 31.27,43.49 v31.58,43.18 35.08,46.67 v49.68,46.67 56.35,46.67 v59.52,43.49 68.41,43.49 v69.69,42.22
OUT_G  (via drill 0.6)
  Top 0.406: IC2.6 50.41,37.87 52.54,40 v52.54,47.62 | v21.42,46.03 IC1.5 | 29.68,44.76 IC1.11 v31.58,44.76 | v69.69,44.76 IC7.11 | IC7.5 61.53,45.93 61.43,46.03 v59.52,46.03
  Bottom 0.406: v21.42,46.03 30.31,46.03 v31.58,44.76 34.44,47.62 v52.54,47.62 57.94,47.62 v59.52,46.03 60.8,44.76 v69.69,44.76
OUT_R  (via drill 0.6)
  Top 0.406: IC2.5 51.21,37.09 53.81,39.68 v53.81,48.57 | v21.42,48.57 IC1.3 | 29.68,48.57 IC1.14 v31.58,48.57 | v69.69,48.57 IC7.14 | v59.52,48.57 IC7.3
  Bottom 0.406: v21.42,48.57 v31.58,48.57 v53.81,48.57 v59.52,48.57 v69.69,48.57
RESET  (via drill 0.6)
  Top 0.406: IC2.20 41.53,31.85 v42.38,32.7
  Bottom 0.406: v42.38,32.7 42.38,34.92 43.65,36.19 43.65,40.64 C5.1 43.33,40.64 43.65,40.95 43.65,42.86 43.48,43.02 R3.2 43.48,43.33 43.65,43.49 SV3.5

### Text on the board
Bottom: AVR-Moodlight2, FB 2008
tDocu: PWM-Out2 | PWM-Out3 | PWM-Out4 | PWM-Out1 | LED- | Supply | - + | ISP6 | 5-15V | DIO | JTAG | I²C | GND | SCL | SDA | Display | Buttons | Analog-In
